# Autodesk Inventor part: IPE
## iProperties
Author: Jan-Steinar
Shininess: 20.0
PropertySet Name: _Private Model Information
Created: 2001-01
Part Number: IPE
Document SubType Name: Modeling
Designer: Jan-Steinar
Control State: 0
Master: False
Checked Out: False
PropertySet Name: Design Tracking Control
Density: 0.0
Volumn: 0.0
Area: 0.0
PropertySet Name: Model Information
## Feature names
1. Extrusion1
